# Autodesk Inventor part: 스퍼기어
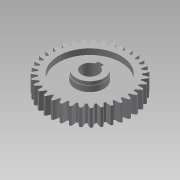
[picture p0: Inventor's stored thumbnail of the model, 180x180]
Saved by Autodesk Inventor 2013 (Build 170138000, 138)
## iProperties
Created: 2013-08
Part Number: 스퍼기어
Material: 강
Document SubType Name: Modeling
Designer: 한국산업디자인학원
Categories: <?xml version="1.0" encoding="UTF-16"?> <MemberInstance><Categories><FamilyTemplate><FamilyTemplateParameter ValueType="xs:double" Id="1" ObjectReferenceKey="da
Density: 1 g/cm^3
Author: 한국산업디자인학원
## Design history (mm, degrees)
sketch "Sketch1"
  geometry: C1 r 37 at (0, 0)
  constraints: 1 centre point
  dimensions: "d0" = 74 diameter of C1 (= da_da)
extrude "Extrusion1" new body sketch "Sketch1" distance "d1" = 15 (= da_b); taper "d2" = 0 deg
workplane "Work Plane2"
feature "피치 지름" dims "d4" = 10, "d5" = 0
workplane "Work Plane8"
workplane "Work Plane9"
feature "스퍼 기어" dims "da_b" = 15, "da_d" = 70, "da_aw" = 70, "da_da" = 74, "da_df" = 65, "da_dw" = 70, angle "da_beta" = 0 deg, "da_lefttooth" = 0, "da_righttooth" = 0
node "작업 평면11"
sketch "스케치3"
  geometry: L1 (-2.5, 9.8)-(2.5, 9.8); L2 (2.5, 9.8)-(2.5, 7.071); L3 (-2.5, 9.8)-(-2.5, 7.071); C1 r 12.5 at (0, 0); A1 r 7.5 centre (0, 0) between (-2.5, 7.071) and (2.5, 7.071); 2 further points
  constraints: 6 end point, 2 centre point, 2 coincident, 2 point on circle, 1 horizontal, 1 midpoint, 1 parallel, 1 perpendicular, 1 vertical alignment
  dimensions: "d50" = 25 diameter of C1; "d51" = 15 diameter of A1; "d52" = 5 distance of L1.start L1.end; "d53" = 9.8 distance from line of point (0, 0) L1
extrude "돌출2" join sketch "스케치3" distance "d54" = 31; taper "d55" = 0 deg
extrude "돌출3" cut sketch "스케치3" distance "d56" = 31; taper "d57" = 0 deg
sketch "스케치4"
  geometry: L1 (-7.5, 18)-(7.071, 18) reference; L2 (7.071, -13)-(-7.5, -13) reference; L3 (-0.214, 18)-(-0.214, -13); L4 (26.715, 15)-(25.858, 15) reference; L5 (27.31, 15)-(22.981, 15) reference; L6 (22.981, 15)-(21.927, 15) reference; L7 (12.5, 18)-(12.5, 15) reference; L8 (-12.5, 18)-(12.5, 18) reference; L9 (-12.5, 15)-(12.5, 15) reference; L10 (12.5, 15)-(27.286, 15); L11 (27.286, 15)-(27.286, 10); L12 (27.286, 10)-(12.5, 10); L13 (12.5, 10)-(12.5, 15); L14 (12.5, 0)-(12.5, -13) reference; L15 (12.5, 0)-(-12.5, 0) reference; L16 (27.286, 0)-(27.286, 5); L17 (27.286, 5)-(12.5, 5); L18 (12.5, 5)-(12.5, 0); L19 (12.5, 0)-(27.286, 0); 1 further point
  constraints: 18 end point, 3 parallel, 2 midpoint, 2 perpendicular, 1 collinear
  dimensions: "d58" = 55 diameter of L11 L3; "d60" = 5 distance of L10.end L11.end; "d61" = 55 diameter of L16 L3; "d64" = 5 distance between parallel lines of L19 L17
revolve "회전1" sketch "스케치4" stored, may be unused: angle "d63" = 90 deg
body "Solid1"
sketch "Sketch2"
  geometry: C1 r 37 at (0, 0) reference; C2 r 35 at (0, 0)
  constraints: 1 centre point, 1 coincident
  dimensions: "d3" = 70 diameter of C2 (= da_dw)
body "Srf1"
node "투영된 루프1"
other parameters: "d17" = 0, "d34" = 0.8976 (computed from da_z), "d39" = 0, "d41" = 0, "d47" = 0, "d48" = 0, "d49" = 3
